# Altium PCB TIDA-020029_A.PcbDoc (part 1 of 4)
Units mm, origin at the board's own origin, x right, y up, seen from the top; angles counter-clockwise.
Board outline 267.5 x 53.5 mm, 2 copper layers (Top Layer, Bottom Layer), stack 1.575 mm thick; 255 components, 134 nets, 990 pads, 1977 vias.
Unrouted connection lines stored in the file: 9.
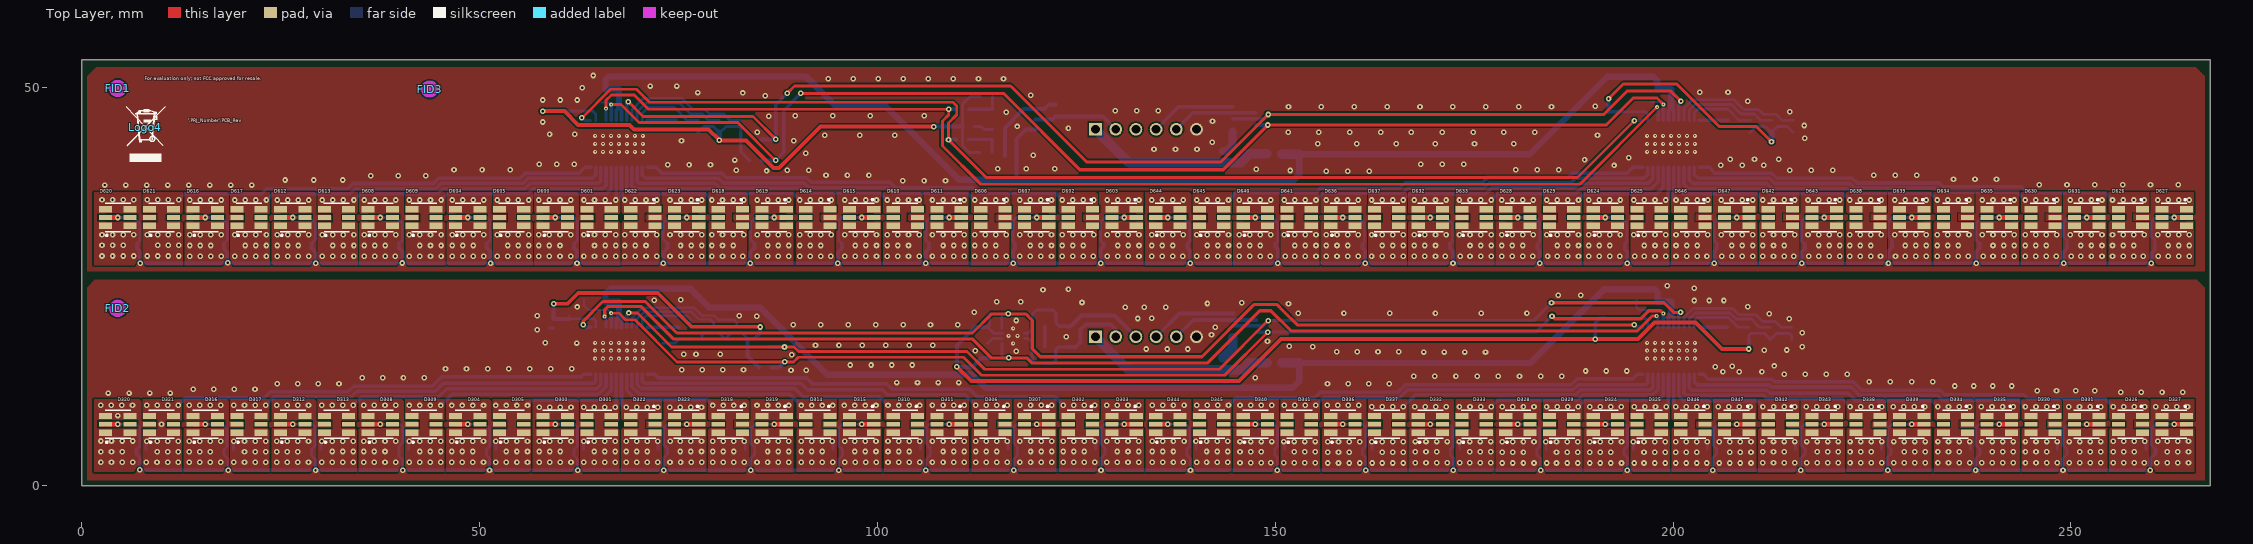
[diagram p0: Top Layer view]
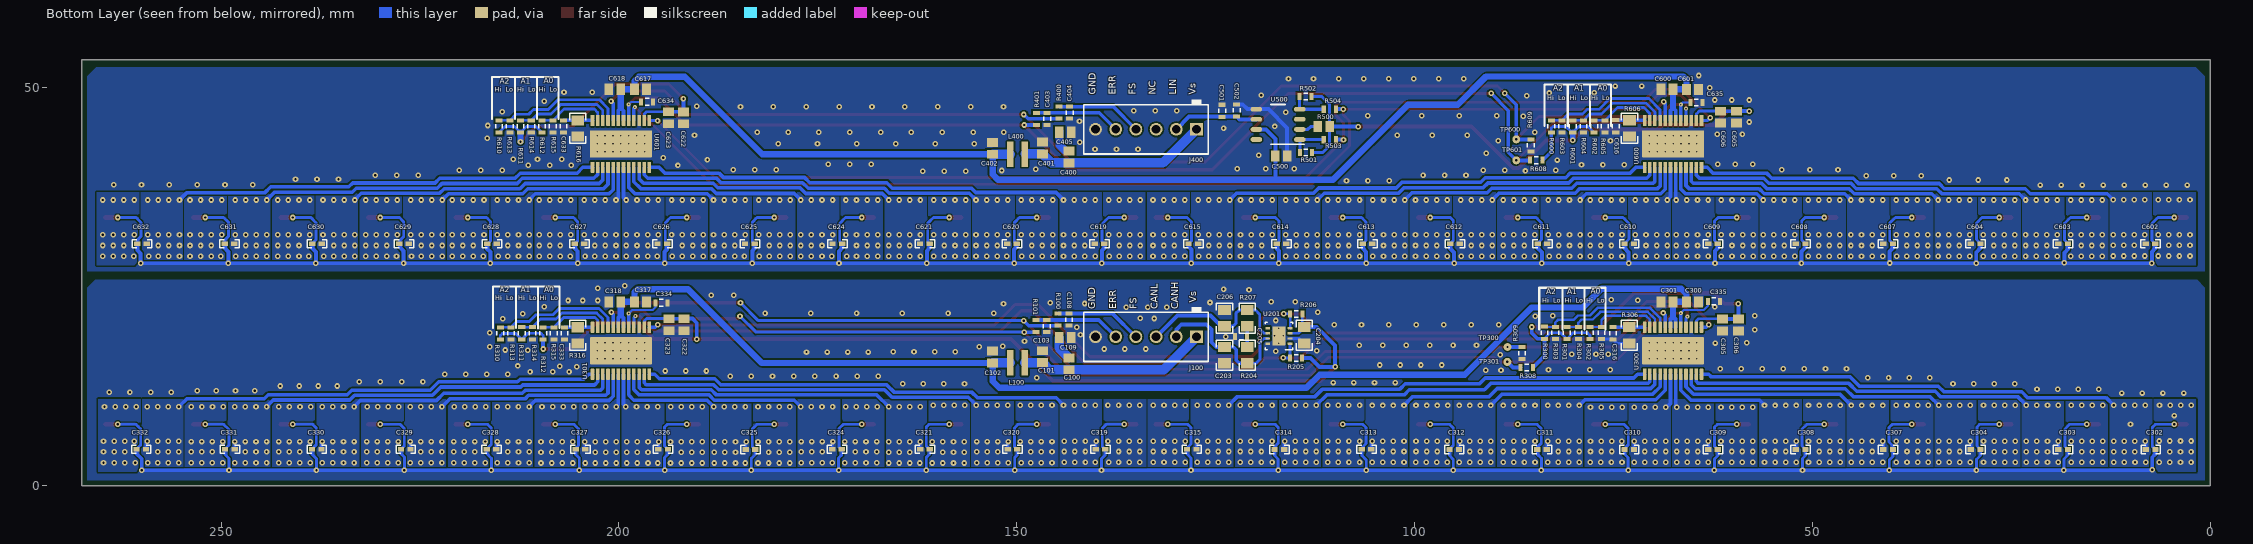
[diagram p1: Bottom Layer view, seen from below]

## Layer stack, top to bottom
Top Solder: solder mask 0.0102, Solder Resist, Dk 3.5
Top Layer: signal copper 0.0356
Dielectric1: core 1.5037, FR-4, Dk 4.8
Bottom Layer: signal copper 0.0356
Bottom Solder: solder mask 0.0102, Solder Resist, Dk 3.5

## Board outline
0,0 267.5,0 267.5,53.5 0,53.5

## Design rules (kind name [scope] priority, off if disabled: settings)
AcuteAngle [All] p1: minimum=4.50000000000000E+0001 checktracksonly=FALSE
AssemblyTestPointUsage [All] p1: valid=2
BoardOutlineClearance BoardOutlineClearance_MountingHoles [OnCopper and InComponentClass('Mounting Holes')] p1: gap=1 ignorepadtopadclearanceinfootprint=FALSE
BoardOutlineClearance BoardOutlineClearance_Poly [OnCopper and IsPoly] p2: gap=0.635 ignorepadtopadclearanceinfootprint=FALSE
BoardOutlineClearance [OnCopper and Not InComponentClass('Logo') and not InComponentClass('FiducialMark') and not InRegion(1000,500,4000,800) and not InPoly] p3: gap=1.5 ignorepadtopadclearanceinfootprint=FALSE
Clearance Clearance_Keepouts [((IsTrack Or IsArc) And Not InPoly) And IsFree and IsKeepOut vs ((IsTrack Or IsArc) And Not InPoly) And IsFree and IsKeepOut] p1: gap=0 ignorepadtopadclearanceinfootprint=FALSE
Clearance Clearance_Poly [InPolygon] p2: gap=0.2 ignorepadtopadclearanceinfootprint=TRUE
Clearance Clearance_FiducialMark [IsKeepOut and InComponentClass('FiducialMark') vs IsPad and InComponentClass('FiducialMark')] p3: gap=0 ignorepadtopadclearanceinfootprint=FALSE
Clearance [All] p4: gap=0.2 ignorepadtopadclearanceinfootprint=TRUE
ComponentClearance ComponentClearance_MountingHoles_FiducialMarks [InComponentClass('Mounting Holes') vs InComponentClass('FiducialMark')] p1: gap=1.27 collisioncheckmode=3 verticalgap=0.254 showdistances=FALSE
ComponentClearance ComponentClearance_Shunt [InComponentClass('Header') vs InComponentClass('Shunt')] p2: gap=0 collisioncheckmode=3 verticalgap=0 showdistances=FALSE
ComponentClearance ComponentClearance_Logo [InComponentClass('Logo')] p3: gap=1.27 collisioncheckmode=3 verticalgap=0.254 showdistances=FALSE
ComponentClearance ComponentClearance_ScrewToNut [(HasFootprint('NY PMS 440 0025 PH')) vs (HasFootprint('Keystone_1902C'))] p4: gap=0.127 collisioncheckmode=3 verticalgap=0.254 showdistances=FALSE
ComponentClearance ComponentClearance_MountingHoles [InComponentClass('Mounting Holes')] p5: gap=6.35 collisioncheckmode=3 verticalgap=2540 showdistances=FALSE
ComponentClearance ComponentClearance_SmallPassives [HasFootprint('0201*') or HasFootprint('0402*') or HasFootprint('0508') or HasFootprint('0603*') or HasFootprint('0612') or HasFootprint('0805*') or HasFootprint('0815*') or HasFootprint('0830*') or HasFootprint('1206*') or HasFootprint('1210*') or HasFootprint('1808*') or HasFootprint('1812*') or HasFootprint('1825*') or HasFootprint('2010*') or HasFootprint('2220*') or HasFootprint('2225*') or HasFootprint('2512*') or HasFootprint('2728*') or HasFootprint('3518*') vs HasFootprint('0201*') or HasFootprint('0402*') or HasFootprint('0508') or HasFootprint('0603*') or HasFootprint('0612') or HasFootprint('0805*') or HasFootprint('0815*') or HasFootprint('0830*') or HasFootprint('1206*') or HasFootprint('1210*') or HasFootprint('1808*') or HasFootprint('1812*') or HasFootprint('1825*') or HasFootprint('2010*') or HasFootprint('2220*') or HasFootprint('2225*') or HasFootprint('2512*') or HasFootprint('2728*') or HasFootprint('3518*')] p6: gap=0.38 collisioncheckmode=3 verticalgap=0.254 showdistances=FALSE
ComponentClearance ComponentClearance_THtoSMT [IsThruComponent vs IsSMTComponent] p7: gap=1.016 collisioncheckmode=3 verticalgap=0.762 showdistances=FALSE
ComponentClearance ComponentClearance_THtoTH [IsThruComponent vs IsThruComponent] p8: gap=0.762 collisioncheckmode=3 verticalgap=0.762 showdistances=FALSE
ComponentClearance [All] p9: gap=0.762 collisioncheckmode=3 verticalgap=0.254 showdistances=FALSE
DiffPairsRouting [All] p1: maxlimit=2.54 minlimit=0.254 mostfreqgap=0.254 toplayer_minwidth=0.381 toplayer_maxwidth=0.381 toplayer_prefwidth=0.381 bottomlayer_minwidth=0.381 bottomlayer_maxwidth=0.381 bottomlayer_prefwidth=0.381 maxuncoupledlength=25.4
FabricationTestPointUsage TestPointUsage [All] p1: valid=2 allowmultiple=FALSE
FabricationTestpoint Testpoint [All] p1: side=3 testpointundercomponent=TRUE minsize=1.016 maxsize=2.54 preferedsize=1.524 minholesize=0 maxholesize=1.016 preferedholesize=0.813 testpointgrid=0.025 allowsidetop=TRUE allowsidebottom=TRUE usegrid=TRUE gridtolerance=0
FanoutControl Fanout_LCC [IsLCC] p1: bgadir=Out bgaviamode=Centered fanoutstyle=Auto fanoutdirection=Alternating viagrid=0.025 // Fanout_LCC (Default Rule)
FanoutControl Fanout_BGA [IsBGA] p2: bgadir=Out bgaviamode=Centered fanoutstyle=Auto fanoutdirection=Alternating viagrid=0.025 // Fanout_BGA (Default Rule)
FanoutControl Fanout_Default [All] p4: bgadir=Out bgaviamode=Centered fanoutstyle=Auto fanoutdirection=Alternating viagrid=0.025 // Fanout_Default (Default Rule)
FanoutControl Fanout_Small [(CompPinCount < 5)] p5: bgadir=Out bgaviamode=Centered fanoutstyle=Auto fanoutdirection=OutThenIn viagrid=0.025 // Fanout_Small (Default Rule)
HoleSize [All] p1: absolutevalues=TRUE maxlimit=6.375 minlimit=0.2 maxpercent=80.000 minpercent=20.000
MinimumAnnularRing MinimumAnnularRing_ThermalPadVias [IsVia and InAnyComponent] p1: minimumring=0.15
MinimumAnnularRing [All] p2: minimumring=0.15
MinimumSolderMaskSliver MinimumSolderMaskSliver_Logo [InComponentClass('Logo') vs InComponentClass('Logo')] p1: minsoldermaskwidth=0.018
MinimumSolderMaskSliver [All] p2: minsoldermaskwidth=0.1
PlaneConnect [All] p1: planeconnectstyle=Direct reliefexpansion=0.254 reliefentries=4 reliefconductorwidth=0.254 reliefairgap=0.254
PolygonConnect [All] p1: connectstyle=Direct reliefconductorwidth=0.254 reliefentries=4 polygonreliefangle="90 Angle" airgapwidth=0.254
RoutingVias ThermalPadVias [IsVia and InAnyComponent] p1: holewidth=0.2 width=0.5 viastyle="Through Hole" minholewidth=0.2 minwidth=0.5 maxholewidth=0.33 maxwidth=0.6
RoutingVias [All] p2: holewidth=0.406 width=0.864 viastyle="Through Hole" minholewidth=0.2 minwidth=0.5 maxholewidth=1.016 maxwidth=1.651
SilkToBoardRegionClearance [Not ((IsComment or IsDesignator) And (Hide <> 'False')) and not InRegion(1000,500,4000,800)] p1:
SilkToSilkClearance SilkToSilkClearance_Pb-FreeLogo [(HasFootprint('Pb-Free_Overlay_Medium') OR HasFootprint('Pb-Free_Overlay_Small')) vs (HasFootprint('Pb-Free_Overlay_Medium') OR HasFootprint('Pb-Free_Overlay_Small'))] p1 off: silktosilkclearance=0
SilkToSilkClearance [All] p2 off: silktosilkclearance=0.1
SilkToSolderMaskClearance SilkToComponentPadClearance [(IsPad or IsFill or IsRegion) and InAnycomponent] p1 off: minsilkscreentomaskgap=0.127 clearancetoexposedcopper=TRUE
SilkToSolderMaskClearance "Silk to Solder Mask Opening" [All] p2 off: minsilkscreentomaskgap=0.1 clearancetoexposedcopper=FALSE
SolderMaskExpansion [All] p1: expansion=0.05
UnRoutedNet [All] p1: checkbadconnections=TRUE
Width [All] p1: maxlimit=2.54 minlimit=0.15 preferedwidth=0.35 checkconnectedcopper=TRUE
14 further rules are at their usual default settings.

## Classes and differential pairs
component class TIDA-020029_A_2: C400 C401 C402 C403 C404 C405 C500 C501 C502 C600 C601 C602 C603 C604 C605 C606 C607 C608 C609 C610 C611 C612 C613 C614 C615 C616 C617 C618 C619 C620 C621 C622 C623 C624 C625 C626 C627 C628 C629 C630 C631 C632 C633 C634 C635 D600 D601 D602 D603 D604 D605 D606 D607 D608 D609 D610 D611 D612 D613 D614 D615 D616 D617 D618 D619 D620 D621 D622 D623 D624 D625 D626 D627 D628 D629 D630 D631 D632 D633 D634 D635 D636 D637 D638 D639 D640 D641 D642 D643 D644 D645 D646 D647 J400 L400 R208 R400 R401 R500 R501 R502 R503 R504 R600 R601 R602 R603 R604 R605 R606 R608 R609 R610 R611 R612 R613 R614 R615 R616 TP600 TP601 U500 U600 U601
component class TIDA-020029_A_1: C100 C101 C102 C103 C108 C109 C203 C204 C205 C206 C300 C301 C302 C303 C304 C305 C306 C307 C308 C309 C310 C311 C312 C313 C314 C315 C316 C317 C318 C319 C320 C321 C322 C323 C324 C325 C326 C327 C328 C329 C330 C331 C332 C333 C334 C335 D300 D301 D302 D303 D304 D305 D306 D307 D308 D309 D310 D311 D312 D313 D314 D315 D316 D317 D318 D319 D320 D321 D322 D323 D324 D325 D326 D327 D328 D329 D330 D331 D332 D333 D334 D335 D336 D337 D338 D339 D340 D341 D342 D343 D344 D345 D346 D347 J100 L100 R100 R101 R204 R205 R206 R207 R300 R301 R302 R303 R304 R305 R306 R308 R309 R310 R311 R312 R313 R314 R315 R316 TP300 TP301 U201 U300 U301
component class TIDA-020029_A_3: FID1 FID2 FID3 Logo3 Logo4 ZZ1 ZZ2 ZZ3 ZZ4
component class FiducialMark: FID1 FID2 FID3
component class AssemblyNote: ZZ1 ZZ2 ZZ3 ZZ4

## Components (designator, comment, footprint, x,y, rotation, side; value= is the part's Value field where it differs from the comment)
C100 "CGA4J2X7R2A473K125AA" 0805L 143.408,15.298 r90 bottom value=0.047uF
C101 "CGA4J1X7R1V475K125AC" 0805L 146.761,16.213 r90 bottom value=4.7uF
C102 "CGA4J1X7R1V475K125AC" 0805L 153.035,16.162 r90 bottom value=4.7uF
C103 "CGA3E2X7R2A102K080AA" 0603S 146.228,20.048 r270 bottom value=1000pF
C108 "CGA3E2X7R2A102K080AA" 0603S 143.434,20.871 r270 bottom value=1000pF
C109 "CGA4J2X7R2A473K125AA" 0805L 143.891,18.6 r180 bottom value=0.047uF
C203 "CGA4J2X7R2A473K125AA" 0805_HV 123.876,16.391 r270 bottom value=0.047uF
C204 "C0805C104K5RACAUTO" 0805_HV 113.843,18.895 r270 bottom value=0.1uF
C205 "CGA3E2C0G1H103J080AA" 0603S 121.793,18.727 r0 bottom value=0.01uF
C206 "CGA4J2X7R2A473K125AA" 0805_HV 123.876,21.039 r90 bottom value=0.047uF
C300 "CGA4J1X7R1V475K125AC" 0805L 65.056,23.096 r180 bottom value=4.7uF
C301 "CGA4J2X8R1H104M125AA" 0805L 68.256,23.096 r0 bottom value=0.1uF
C302 "CGA2B2C0G1H102J050BA" 0402 7.459,4.535 r0 bottom value=1000pF
C303 "CGA2B2C0G1H102J050BA" 0402 18.459,4.535 r0 bottom value=1000pF
C304 "CGA2B2C0G1H102J050BA" 0402 29.459,4.535 r0 bottom value=1000pF
C305 "CGA4J1X7R1V475K125AC" 0805L 61.279,20.193 r270 bottom value=4.7uF
C306 "CGA4J2X8R1H104M125AA" 0805L 59.279,20.193 r270 bottom value=0.1uF
C307 "CGA2B2C0G1H102J050BA" 0402 40.459,4.535 r0 bottom value=1000pF
C308 "CGA2B2C0G1H102J050BA" 0402 51.459,4.535 r0 bottom value=1000pF
C309 "CGA2B2C0G1H102J050BA" 0402 62.459,4.535 r0 bottom value=1000pF
C310 "CGA2B2C0G1H102J050BA" 0402 73.004,4.535 r180 bottom value=1000pF
C311 "CGA2B2C0G1H102J050BA" 0402 83.972,4.535 r180 bottom value=1000pF
C312 "CGA2B2C0G1H102J050BA" 0402 95.004,4.535 r180 bottom value=1000pF
C313 "CGA2B2C0G1H102J050BA" 0402 106.02,4.561 r180 bottom value=1000pF
C314 "CGA2B2C0G1H102J050BA" 0402 116.992,4.535 r180 bottom value=1000pF
C315 "CGA2B2C0G1H102J050BA" 0402 128.004,4.561 r180 bottom value=1000pF
C316 "CGA3E2C0G1H103J080AA" 0603S 75.058,19.15 r90 bottom value=0.01uF
C317 "CGA4J1X7R1V475K125AC" 0805L 197.294,23.096 r180 bottom value=4.7uF
C318 "CGA4J2X8R1H104M125AA" 0805L 200.52,23.096 r0 bottom value=0.1uF
C319 "CGA2B2C0G1H102J050BA" 0402 139.471,4.561 r0 bottom value=1000pF
C320 "CGA2B2C0G1H102J050BA" 0402 150.546,4.569 r0 bottom value=1000pF
C321 "CGA2B2C0G1H102J050BA" 0402 161.544,4.561 r0 bottom value=1000pF
C322 "CGA4J1X7R1V475K125AC" 0805L 191.828,20.218 r270 bottom value=4.7uF
C323 "CGA4J2X8R1H104M125AA" 0805L 193.73,20.218 r270 bottom value=0.1uF
C324 "CGA2B2C0G1H102J050BA" 0402 172.593,4.561 r0 bottom value=1000pF
C325 "CGA2B2C0G1H102J050BA" 0402 183.459,4.535 r0 bottom value=1000pF
C326 "CGA2B2C0G1H102J050BA" 0402 194.439,4.561 r0 bottom value=1000pF
C327 "CGA2B2C0G1H102J050BA" 0402 204.85,4.561 r180 bottom value=1000pF
C328 "CGA2B2C0G1H102J050BA" 0402 216.006,4.561 r180 bottom value=1000pF
C329 "CGA2B2C0G1H102J050BA" 0402 226.804,4.561 r180 bottom value=1000pF
C330 "CGA2B2C0G1H102J050BA" 0402 237.988,4.561 r180 bottom value=1000pF
C331 "CGA2B2C0G1H102J050BA" 0402 248.912,4.561 r180 bottom value=1000pF
C332 "CGA2B2C0G1H102J050BA" 0402 260.045,4.561 r180 bottom value=1000pF
C333 "CGA3E2C0G1H103J080AA" 0603S 206.836,19.134 r90 bottom value=0.01uF
C334 "CGA3E2X7R2A102K080AA" 0603S 194.669,22.966 r180 bottom value=1000pF
C335 "CGA3E2X7R2A102K080AA" 0603S 62.359,23.165 r180 bottom value=1000pF
C400 "CGA4J2X7R2A473K125AA" 0805L 143.408,41.308 r90 bottom value=0.047uF
C401 "CGA4J1X7R1V475K125AC" 0805L 146.761,42.435 r90 bottom value=4.7uF
C402 "CGA4J1X7R1V475K125AC" 0805L 153.035,42.385 r90 bottom value=4.7uF
C403 "CGA3E2X7R2A102K080AA" 0603S 146.177,46.09 r270 bottom value=1000pF
C404 "CGA3E2X7R2A102K080AA" 0603S 143.341,46.877 r270 bottom value=1000pF
C405 "CGA4J2X7R2A473K125AA" 0805L 143.891,44.413 r180 bottom value=0.047uF
C500 "CGA4J2X8R1H104M125AA" 0805L 116.75,41.448 r180 bottom value=0.1uF
C501 "CGA3E2NP01H101J080AA" 0603S 124.181,47.106 r90 bottom value=100pF
C502 "CGA3E2NP01H101J080AA" 0603S 122.352,47.157 r90 bottom value=100pF
C600 "CGA4J1X7R1V475K125AC" 0805L 68.256,49.824 r0 bottom value=4.7uF
C601 "CGA4J2X8R1H104M125AA" 0805L 65.056,49.798 r180 bottom value=0.1uF
C602 "CGA2B2C0G1H102J050BA" 0402 7.5,30.4 r0 bottom value=1000pF
C603 "CGA2B2C0G1H102J050BA" 0402 18.459,30.4 r0 bottom value=1000pF
C604 "CGA2B2C0G1H102J050BA" 0402 29.459,30.4 r0 bottom value=1000pF
C605 "CGA4J1X7R1V475K125AC" 0805L 59.546,46.311 r270 bottom value=4.7uF
C606 "CGA4J2X8R1H104M125AA" 0805L 61.546,46.311 r270 bottom value=0.1uF
C607 "CGA2B2C0G1H102J050BA" 0402 40.459,30.4 r0 bottom value=1000pF
C608 "CGA2B2C0G1H102J050BA" 0402 51.459,30.4 r0 bottom value=1000pF
C609 "CGA2B2C0G1H102J050BA" 0402 62.459,30.4 r0 bottom value=1000pF
C610 "CGA2B2C0G1H102J050BA" 0402 73.004,30.4 r180 bottom value=1000pF
C611 "CGA2B2C0G1H102J050BA" 0402 83.9,30.4 r180 bottom value=1000pF
C612 "CGA2B2C0G1H102J050BA" 0402 94.919,30.4 r180 bottom value=1000pF
C613 "CGA2B2C0G1H102J050BA" 0402 105.9,30.4 r180 bottom value=1000pF
C614 "CGA2B2C0G1H102J050BA" 0402 116.7,30.4 r180 bottom value=1000pF
C615 "CGA2B2C0G1H102J050BA" 0402 127.8,30.4 r180 bottom value=1000pF
C616 "CGA3E2C0G1H103J080AA" 0603S 74.701,45.166 r90 bottom value=0.01uF
C617 "CGA4J1X7R1V475K125AC" 0805L 197.294,49.824 r180 bottom value=4.7uF
C618 "CGA4J2X8R1H104M125AA" 0805L 200.52,49.824 r0 bottom value=0.1uF
C619 "CGA2B2C0G1H102J050BA" 0402 139.579,30.4 r0 bottom value=1000pF
C620 "CGA2B2C0G1H102J050BA" 0402 150.613,30.4 r0 bottom value=1000pF
C621 "CGA2B2C0G1H102J050BA" 0402 161.55,30.4 r0 bottom value=1000pF
C622 "CGA4J1X7R1V475K125AC" 0805L 191.893,46.217 r270 bottom value=4.7uF
C623 "CGA4J2X8R1H104M125AA" 0805L 193.777,46.235 r270 bottom value=0.1uF
C624 "CGA2B2C0G1H102J050BA" 0402 172.55,30.4 r0 bottom value=1000pF
C625 "CGA2B2C0G1H102J050BA" 0402 183.55,30.4 r0 bottom value=1000pF
C626 "CGA2B2C0G1H102J050BA" 0402 194.55,30.4 r0 bottom value=1000pF
C627 "CGA2B2C0G1H102J050BA" 0402 204.95,30.4 r180 bottom value=1000pF
C628 "CGA2B2C0G1H102J050BA" 0402 215.95,30.4 r180 bottom value=1000pF
C629 "CGA2B2C0G1H102J050BA" 0402 227,30.4 r180 bottom value=1000pF
C630 "CGA2B2C0G1H102J050BA" 0402 237.95,30.4 r180 bottom value=1000pF
C631 "CGA2B2C0G1H102J050BA" 0402 248.95,30.4 r180 bottom value=1000pF
C632 "CGA2B2C0G1H102J050BA" 0402 259.95,30.4 r180 bottom value=1000pF
C633 "CGA3E2C0G1H103J080AA" 0603S 206.963,45.15 r90 bottom value=0.01uF
C634 "CGA3E2X7R2A102K080AA" 0603S 196.468,48.241 r180 bottom value=1000pF
C635 "CGA3E2X7R2A102K080AA" 0603S 64.556,48.165 r180 bottom value=1000pF
D300 "LR G6SP-CBEA-1-1-Z" LED_LR_G6SP 59.5,7.7 r90 top value=Red
D301 "LR G6SP-CBEA-1-1-Z" LED_LR_G6SP 65,7.7 r90 top value=Red
D302 "LR G6SP-CBEA-1-1-Z" LED_LR_G6SP 125.5,7.7 r270 top value=Red
D303 "LR G6SP-CBEA-1-1-Z" LED_LR_G6SP 131,7.7 r270 top value=Red
D304 "LR G6SP-CBEA-1-1-Z" LED_LR_G6SP 48.5,7.7 r90 top value=Red
D305 "LR G6SP-CBEA-1-1-Z" LED_LR_G6SP 54,7.7 r90 top value=Red
D306 "LR G6SP-CBEA-1-1-Z" LED_LR_G6SP 114.5,7.7 r270 top value=Red
D307 "LR G6SP-CBEA-1-1-Z" LED_LR_G6SP 120,7.7 r270 top value=Red
D308 "LR G6SP-CBEA-1-1-Z" LED_LR_G6SP 37.5,7.7 r90 top value=Red
D309 "LR G6SP-CBEA-1-1-Z" LED_LR_G6SP 43,7.7 r90 top value=Red
D310 "LR G6SP-CBEA-1-1-Z" LED_LR_G6SP 103.5,7.7 r270 top value=Red
D311 "LR G6SP-CBEA-1-1-Z" LED_LR_G6SP 109,7.7 r270 top value=Red
D312 "LR G6SP-CBEA-1-1-Z" LED_LR_G6SP 26.5,7.7 r90 top value=Red
D313 "LR G6SP-CBEA-1-1-Z" LED_LR_G6SP 32,7.7 r90 top value=Red
D314 "LR G6SP-CBEA-1-1-Z" LED_LR_G6SP 92.5,7.7 r270 top value=Red
D315 "LR G6SP-CBEA-1-1-Z" LED_LR_G6SP 98,7.7 r270 top value=Red
D316 "LR G6SP-CBEA-1-1-Z" LED_LR_G6SP 15.5,7.7 r90 top value=Red
D317 "LR G6SP-CBEA-1-1-Z" LED_LR_G6SP 21,7.7 r90 top value=Red
D318 "LR G6SP-CBEA-1-1-Z" LED_LR_G6SP 81.5,7.7 r270 top value=Red
D319 "LR G6SP-CBEA-1-1-Z" LED_LR_G6SP 87,7.7 r270 top value=Red
D320 "LR G6SP-CBEA-1-1-Z" LED_LR_G6SP 4.5,7.7 r90 top value=Red
D321 "LR G6SP-CBEA-1-1-Z" LED_LR_G6SP 10,7.7 r90 top value=Red
D322 "LR G6SP-CBEA-1-1-Z" LED_LR_G6SP 70.5,7.7 r270 top value=Red
D323 "LR G6SP-CBEA-1-1-Z" LED_LR_G6SP 76,7.7 r270 top value=Red
D324 "LR G6SP-CBEA-1-1-Z" LED_LR_G6SP 191.5,7.7 r90 top value=Red
D325 "LR G6SP-CBEA-1-1-Z" LED_LR_G6SP 197,7.7 r90 top value=Red
D326 "LR G6SP-CBEA-1-1-Z" LED_LR_G6SP 257.5,7.7 r270 top value=Red
D327 "LR G6SP-CBEA-1-1-Z" LED_LR_G6SP 263,7.7 r270 top value=Red
D328 "LR G6SP-CBEA-1-1-Z" LED_LR_G6SP 180.5,7.7 r90 top value=Red
D329 "LR G6SP-CBEA-1-1-Z" LED_LR_G6SP 186,7.7 r90 top value=Red
D330 "LR G6SP-CBEA-1-1-Z" LED_LR_G6SP 246.5,7.7 r270 top value=Red
D331 "LR G6SP-CBEA-1-1-Z" LED_LR_G6SP 252,7.7 r270 top value=Red
D332 "LR G6SP-CBEA-1-1-Z" LED_LR_G6SP 169.5,7.7 r90 top value=Red
D333 "LR G6SP-CBEA-1-1-Z" LED_LR_G6SP 175,7.7 r90 top value=Red
D334 "LR G6SP-CBEA-1-1-Z" LED_LR_G6SP 235.5,7.7 r270 top value=Red
D335 "LR G6SP-CBEA-1-1-Z" LED_LR_G6SP 241,7.7 r270 top value=Red
D336 "LR G6SP-CBEA-1-1-Z" LED_LR_G6SP 158.5,7.7 r90 top value=Red
D337 "LR G6SP-CBEA-1-1-Z" LED_LR_G6SP 164,7.7 r90 top value=Red
D338 "LR G6SP-CBEA-1-1-Z" LED_LR_G6SP 224.5,7.7 r270 top value=Red
D339 "LR G6SP-CBEA-1-1-Z" LED_LR_G6SP 230,7.7 r270 top value=Red
D340 "LR G6SP-CBEA-1-1-Z" LED_LR_G6SP 147.5,7.7 r90 top value=Red
D341 "LR G6SP-CBEA-1-1-Z" LED_LR_G6SP 153,7.7 r90 top value=Red
D342 "LR G6SP-CBEA-1-1-Z" LED_LR_G6SP 213.5,7.7 r270 top value=Red
D343 "LR G6SP-CBEA-1-1-Z" LED_LR_G6SP 219,7.7 r270 top value=Red
D344 "LR G6SP-CBEA-1-1-Z" LED_LR_G6SP 136.5,7.7 r90 top value=Red
D345 "LR G6SP-CBEA-1-1-Z" LED_LR_G6SP 142,7.7 r90 top value=Red
D346 "LR G6SP-CBEA-1-1-Z" LED_LR_G6SP 202.5,7.7 r270 top value=Red
D347 "LR G6SP-CBEA-1-1-Z" LED_LR_G6SP 208,7.7 r270 top value=Red
D600 "LR G6SP-CBEA-1-1-Z" LED_LR_G6SP 59.5,33.7 r90 top value=Red
D601 "LR G6SP-CBEA-1-1-Z" LED_LR_G6SP 65,33.7 r90 top value=Red
D602 "LR G6SP-CBEA-1-1-Z" LED_LR_G6SP 125.5,33.7 r270 top value=Red
D603 "LR G6SP-CBEA-1-1-Z" LED_LR_G6SP 131,33.7 r270 top value=Red
D604 "LR G6SP-CBEA-1-1-Z" LED_LR_G6SP 48.5,33.7 r90 top value=Red
D605 "LR G6SP-CBEA-1-1-Z" LED_LR_G6SP 54,33.7 r90 top value=Red
D606 "LR G6SP-CBEA-1-1-Z" LED_LR_G6SP 114.5,33.7 r270 top value=Red
D607 "LR G6SP-CBEA-1-1-Z" LED_LR_G6SP 120,33.7 r270 top value=Red
D608 "LR G6SP-CBEA-1-1-Z" LED_LR_G6SP 37.5,33.7 r90 top value=Red
D609 "LR G6SP-CBEA-1-1-Z" LED_LR_G6SP 43,33.7 r90 top value=Red
D610 "LR G6SP-CBEA-1-1-Z" LED_LR_G6SP 103.5,33.7 r270 top value=Red
D611 "LR G6SP-CBEA-1-1-Z" LED_LR_G6SP 109,33.7 r270 top value=Red
D612 "LR G6SP-CBEA-1-1-Z" LED_LR_G6SP 26.5,33.7 r90 top value=Red
D613 "LR G6SP-CBEA-1-1-Z" LED_LR_G6SP 32,33.7 r90 top value=Red
D614 "LR G6SP-CBEA-1-1-Z" LED_LR_G6SP 92.5,33.7 r270 top value=Red
D615 "LR G6SP-CBEA-1-1-Z" LED_LR_G6SP 98,33.7 r270 top value=Red
D616 "LR G6SP-CBEA-1-1-Z" LED_LR_G6SP 15.5,33.7 r90 top value=Red
D617 "LR G6SP-CBEA-1-1-Z" LED_LR_G6SP 21,33.7 r90 top value=Red
D618 "LR G6SP-CBEA-1-1-Z" LED_LR_G6SP 81.5,33.7 r270 top value=Red
D619 "LR G6SP-CBEA-1-1-Z" LED_LR_G6SP 87,33.7 r270 top value=Red
D620 "LR G6SP-CBEA-1-1-Z" LED_LR_G6SP 4.5,33.7 r90 top value=Red
D621 "LR G6SP-CBEA-1-1-Z" LED_LR_G6SP 10,33.7 r90 top value=Red
D622 "LR G6SP-CBEA-1-1-Z" LED_LR_G6SP 70.5,33.7 r270 top value=Red
D623 "LR G6SP-CBEA-1-1-Z" LED_LR_G6SP 76,33.7 r270 top value=Red
D624 "LR G6SP-CBEA-1-1-Z" LED_LR_G6SP 191.5,33.7 r90 top value=Red
D625 "LR G6SP-CBEA-1-1-Z" LED_LR_G6SP 197,33.7 r90 top value=Red
D626 "LR G6SP-CBEA-1-1-Z" LED_LR_G6SP 257.5,33.7 r270 top value=Red
D627 "LR G6SP-CBEA-1-1-Z" LED_LR_G6SP 263,33.7 r270 top value=Red
D628 "LR G6SP-CBEA-1-1-Z" LED_LR_G6SP 180.5,33.7 r90 top value=Red
D629 "LR G6SP-CBEA-1-1-Z" LED_LR_G6SP 186,33.7 r90 top value=Red
D630 "LR G6SP-CBEA-1-1-Z" LED_LR_G6SP 246.5,33.7 r270 top value=Red
D631 "LR G6SP-CBEA-1-1-Z" LED_LR_G6SP 252,33.7 r270 top value=Red
D632 "LR G6SP-CBEA-1-1-Z" LED_LR_G6SP 169.5,33.7 r90 top value=Red
D633 "LR G6SP-CBEA-1-1-Z" LED_LR_G6SP 175,33.7 r90 top value=Red
D634 "LR G6SP-CBEA-1-1-Z" LED_LR_G6SP 235.5,33.7 r270 top value=Red
D635 "LR G6SP-CBEA-1-1-Z" LED_LR_G6SP 241,33.7 r270 top value=Red
D636 "LR G6SP-CBEA-1-1-Z" LED_LR_G6SP 158.5,33.7 r90 top value=Red
D637 "LR G6SP-CBEA-1-1-Z" LED_LR_G6SP 164,33.7 r90 top value=Red
D638 "LR G6SP-CBEA-1-1-Z" LED_LR_G6SP 224.5,33.7 r270 top value=Red
D639 "LR G6SP-CBEA-1-1-Z" LED_LR_G6SP 230,33.7 r270 top value=Red
D640 "LR G6SP-CBEA-1-1-Z" LED_LR_G6SP 147.5,33.7 r90 top value=Red
D641 "LR G6SP-CBEA-1-1-Z" LED_LR_G6SP 153,33.7 r90 top value=Red
D642 "LR G6SP-CBEA-1-1-Z" LED_LR_G6SP 213.5,33.7 r270 top value=Red
D643 "LR G6SP-CBEA-1-1-Z" LED_LR_G6SP 219,33.7 r270 top value=Red
D644 "LR G6SP-CBEA-1-1-Z" LED_LR_G6SP 136.5,33.7 r90 top value=Red
D645 "LR G6SP-CBEA-1-1-Z" LED_LR_G6SP 142,33.7 r90 top value=Red
D646 "LR G6SP-CBEA-1-1-Z" LED_LR_G6SP 202.5,33.7 r270 top value=Red
D647 "LR G6SP-CBEA-1-1-Z" LED_LR_G6SP 208,33.7 r270 top value=Red
FID1 "Fiducial" Fiducial10-20 4.496,49.918 r0 top
FID2 "Fiducial" Fiducial10-20 4.496,22.276 r0 top
FID3 "Fiducial" Fiducial10-20 43.713,49.841 r0 top
J100 "1725698" Phoenix_1725698 133.75,18.7 r0 bottom
J400 "1725698" Phoenix_1725698 133.75,44.782 r0 bottom
L100 "XEL3530-122MEC" FP-XEL3530-122MEC_SMT_IND_3MM2_3MM5-MFG 149.9,15.425 r0 bottom
L400 "XEL3530-122MEC" FP-XEL3530-122MEC_SMT_IND_3MM2_3MM5-MFG 149.9,41.635 r0 bottom
Logo3 "FCC disclaimer" FCC_disclaimer 65.938,83.007 r0 top
Logo4 "WEEE logo" WEEE_Minimum 7.976,45.06 r0 top
R100 "RCS06030000Z0EA" 0603S 144.805,20.871 r270 bottom value=0
R101 "RCS06030000Z0EA" 0603S 147.588,20.048 r270 bottom value=0
R204 "CRCW080560R4FKEA" 0805_HV 121.031,16.391 r270 bottom value=60.4
R205 "RMCF0603FT10K0" 0603S 114.884,16.048 r180 bottom value=10.0k
R206 "RMCF0603FT10K0" 0603S 114.859,21.572 r180 bottom value=10.0k
R207 "CRCW080560R4FKEA" 0805_HV 121.031,21.039 r270 bottom value=60.4
R300 "RMCF0603FT10K0" 0603S 83.648,19.21 r270 bottom value=10.0k
R301 "RMCF0603FT10K0" 0603S 80.85,19.2 r270 bottom value=10.0k
R302 "RMCF0603FT10K0" 0603S 77.95,19.2 r270 bottom value=10.0k
R303 "RMCF0603FT10K0" 0603S 82.3,19.2 r90 bottom value=10.0k
R304 "RMCF0603FT10K0" 0603S 79.4,19.2 r90 bottom value=10.0k
R305 "RMCF0603FT10K0" 0603S 76.5,19.2 r90 bottom value=10.0k
R306 "ERJ-6ENF1242V" 0805_HV 73,18.9 r90 bottom value=12.4k
R308 "RMCF0603FT10K0" 0603S 85.894,14.842 r180 bottom value=10.0k
R309 "RMCF0603FT10K0" 0603S 86.479,16.659 r90 bottom value=10.0k
R310 "RMCF0603FT10K0" 0603S 214.913,19.134 r270 bottom value=10.0k
R311 "RMCF0603FT10K0" 0603S 212.221,19.144 r270 bottom value=10.0k
R312 "RMCF0603FT10K0" 0603S 209.529,19.134 r270 bottom value=10.0k
R313 "RMCF0603FT10K0" 0603S 213.567,19.134 r90 bottom value=10.0k
R314 "RMCF0603FT10K0" 0603S 210.875,19.144 r90 bottom value=10.0k
R315 "RMCF0603FT10K0" 0603S 208.185,19.135 r90 bottom value=10.0k
R316 "ERJ-6ENF1242V" 0805_HV 205.185,18.88 r90 bottom value=12.4k
R400 "RCS06030000Z0EA" 0603S 144.678,46.877 r270 bottom value=0
R401 "RCS06030000Z0EA" 0603S 147.523,46.09 r270 bottom value=0
R500 "ERJ-P06F4701V" 0805L 111.404,45.125 r0 bottom value=4.70k
R501 "RMCF0603FT10K0" 0603S 113.64,41.873 r180 bottom value=10.0k
R502 "RMCF0603FT10K0" 0603S 113.69,48.909 r180 bottom value=10.0k
R503 "CRCW060322R0JNEA" 0603S 110.646,43.474 r0 bottom value=22
R504 "CRCW060322R0JNEA" 0603S 110.646,47.309 r0 bottom value=22
R600 "RMCF0603FT10K0" 0603S 82.804,45.15 r270 bottom value=10.0k
R601 "RMCF0603FT10K0" 0603S 80.112,45.15 r270 bottom value=10.0k
R602 "RMCF0603FT10K0" 0603S 77.419,45.15 r270 bottom value=10.0k
R603 "RMCF0603FT10K0" 0603S 81.458,45.15 r90 bottom value=10.0k
R604 "RMCF0603FT10K0" 0603S 78.765,45.15 r90 bottom value=10.0k
R605 "RMCF0603FT10K0" 0603S 76.073,45.15 r90 bottom value=10.0k
R606 "ERJ-6ENF1242V" 0805_HV 72.974,44.906 r90 bottom value=12.4k
R608 "RMCF0603FT10K0" 0603S 84.693,40.901 r180 bottom value=10.0k
R609 "RMCF0603FT10K0" 0603S 85.379,42.755 r90 bottom value=10.0k
R610 "RMCF0603FT10K0" 0603S 215.066,45.15 r270 bottom value=10.0k
R611 "RMCF0603FT10K0" 0603S 212.373,45.15 r270 bottom value=10.0k
R612 "RMCF0603FT10K0" 0603S 209.681,45.15 r270 bottom value=10.0k
R613 "RMCF0603FT10K0" 0603S 213.72,45.15 r90 bottom value=10.0k
R614 "RMCF0603FT10K0" 0603S 211.027,45.15 r90 bottom value=10.0k
R615 "RMCF0603FT10K0" 0603S 208.309,45.15 r90 bottom value=10.0k
R616 "ERJ-6ENF1242V" 0805_HV 205.185,44.896 r90 bottom value=12.4k
TP300 "TP_SM_1MM" TP_SM_1MM 88.309,17.421 r270 bottom
TP301 "TP_SM_1MM" TP_SM_1MM 88.332,15.542 r270 bottom
TP600 "TP_SM_1MM" TP_SM_1MM 87.208,43.517 r270 bottom
TP601 "TP_SM_1MM" TP_SM_1MM 87.208,40.875 r270 bottom
U201 "TCAN1044DRBTQ1" DRB0008F 117.043,18.819 r0 bottom
U300 "TPS929120QPWPRQ1" PWP0024P_N 67.5,16.95 r270 bottom
U301 "TPS929120QPWPRQ1" PWP0024P_N 199.75,16.95 r270 bottom
U500 "TLIN1029DRQ1" D0008A_N 117.145,45.404 r0 bottom
U600 "TPS929120QPWPRQ1" PWP0024P_N 67.5,42.95 r270 bottom
U601 "TPS929120QPWPRQ1" PWP0024P_N 199.75,42.95 r270 bottom
ZZ1 "This Assembly Note is for PCB labels only" AssemblyNoteLabel 4.699,100.025 r0 top
ZZ2 "These assemblies are ESD sensitive, ESD precautions shall be observed." AssemblyNote 4.699,97.259 r0 top
ZZ3 "These assemblies must be clean and free from flux and all contaminants. Use of no clean flux is not acceptable." AssemblyNote 4.699,95.01 r0 top
ZZ4 "These assemblies must comply with workmanship standards IPC-A-610 Class 2, unless otherwise specified." AssemblyNote 4.699,92.761 r0 top

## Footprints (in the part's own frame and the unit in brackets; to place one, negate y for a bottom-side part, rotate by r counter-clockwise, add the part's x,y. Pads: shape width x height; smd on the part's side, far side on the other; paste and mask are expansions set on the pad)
0402 [mm] "0402 from SM-752 data"
  rect 0.8x0.6 smd: 1(-0.6,0) 2(0.6,0)
  silkscreen extent -1.22,-0.52 1.22,0.52, body extent -0.55,-0.3 0.55,0.3, height 0.6
0603S [mil]
  rect 20x35 smd: 1(-30,0) 2(30,0)
  silkscreen extent -10,-17 10,17, body extent -34,-19 34,19, height 39
0805_HV [mil] "0805 with 30mil clearance between pads"
  rect 50x63 smd: 1(-40,0) 2(40,0)
  silkscreen extent -74,-40 74,40, body extent -43,-29 43,29, height 57
0805L [mm] "0805 from SM-752 data"
  rect 1.1x1.4 smd: 1(-0.75,0) 2(0.75,0)
  body extent -1.1,-0.72 1.1,0.72, height 1.45
AssemblyNote [mm] "Assembly Note"
AssemblyNoteLabel [mm] "Assembly Note for PCB Labels"
D0008A_N [mm] "SOIC, 8-Leads, Body 4.9x3.9mm, Pitch 1.27mm, IPC Medium Density"
  oval 1.45x0.6 smd: 1(-2.725,1.905) 2(-2.725,0.635) 3(-2.725,-0.635) 4(-2.725,-1.905) 5(2.725,-1.905) 6(2.725,-0.635) 7(2.725,0.635) 8(2.725,1.905)
  silkscreen extent -3.3,-2.5 0.9,2.5, body extent -3,-2.45 3,2.45, height 1.63
DRB0008F [mm] "SON, 8-Leads, Body 3x3mm, Pitch 0.65mm, Thermal Pad 2.4x1.6mm, TI Recommended"
  rrect33% 0.6x0.3 smd: 1(-1.4,0.975) 2(-1.4,0.325) 3(-1.4,-0.325) 4(-1.4,-0.975) 5(1.4,-0.975) 6(1.4,-0.325) 7(1.4,0.325) 8(1.4,0.975)
  rrect9% 1.47x1.07 on Bottom Paste: 9(0,-0.635) 9(0,0.635)
  rrect6% 1.6x2.4 smd paste-1.2: 9(0,0)
  silkscreen extent -1.73,-1.73 1.73,1.73, body extent -1.5,-1.5 1.5,1.5, height 0.77
FCC_disclaimer [mm]
Fiducial10-20 [mm]
  round 1 smd mask+0.5: 1(0,0)
  Top Layer keep-out circle w1.178: c0,0 r0.5
FP-XEL3530-122MEC_SMT_IND_3MM2_3MM5-MFG [mm]
  rrect12% 0.81x3.2 smd paste+0 mask+0: 1(-0.9,0) 2(0.9,0)
  body extent -1.6,-1.75 1.6,1.75, height 3
LED_LR_G6SP [mm] "OSRAM"
  rect 0.8x1.65 smd: 1(-1.05,1.525) 3(1.05,1.525) 4(1.05,-1.525) 6(-1.05,-1.525)
  rect 0.6x1.65 smd: 2(0,1.525) 5(0,-1.525)
  silkscreen extent -2.35,-1.63 1.78,1.6, body extent -1.75,-1.6 1.75,1.6, height 2.12
Phoenix_1725698 [mm] "Terminal Block, 6x1, 2.54mm, TH"
  rect 1.6x1.6 hole 1.1: 1(-6.35,0)
  round 1.6 hole 1.1: 2(-3.81,0) 3(-1.27,0) 4(1.27,0) 5(3.81,0) 6(6.35,0)
  silkscreen extent -7.85,-3.75 7.85,3.1, body extent -7.85,-3.1 7.85,3.1, height 8.51
PWP0024P_N [mm] "HTTSOP-24"
  rrect22% 1.4x0.45 smd: 1(-2.95,3.575) 2(-2.95,2.925) 3(-2.95,2.275) 4(-2.95,1.625) 5(-2.95,0.975) 6(-2.95,0.325) 7(-2.95,-0.325) 8(-2.95,-0.975) 9(-2.95,-1.625) 10(-2.95,-2.275) 11(-2.95,-2.925) 12(-2.95,-3.575) 13(2.95,-3.575) 14(2.95,-2.925) 15(2.95,-2.275) 16(2.95,-1.625) 17(2.95,-0.975) 18(2.95,-0.325) 19(2.95,0.325) 20(2.95,0.975) 21(2.95,1.625) 22(2.95,2.275) 23(2.95,2.925) 24(2.95,3.575)
  rrect6% 3.4x7.8 smd paste-2 mask-2: 25(0,0)
  body extent -3.21,-3.9 3.21,3.9, height 1.2
TP_SM_1MM [mm] "1mm Test Point, SMT"
  round 1 smd paste-0.5: 1(0,0)
WEEE_Minimum [mm] "WEEElie bin"
  silkscreen extent -2.42,-4.38 2.52,2.65

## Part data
C100 C109 C203 C206 C400 C405: library part CMP-0007970-1, "CAP, CERM, 0.047 uF, 100 V, +/- 10%, X7R, AEC-Q200 Grade 1, 0805", Cap_Case=0805, Manufacturer=TDK, Supplier Part Number 1=445-5825-1-ND, TempCo=X7R, Tolerance_%=10%, Value1="0.049089 ohm", Value2=100V, ValueDisplayed=0.047uF
C101 C102 C300 C305 C317 C322 C401 C402 C600 C605 C617 C622: library part CMP-0007964-1, "CAP, CERM, 4.7 uF, 35 V, +/- 10%, X7R, AEC-Q200 Grade 1, 0805", Cap_Case=0805, Manufacturer=TDK, Supplier Part Number 1=810-CGA4J1X7R1V475K125AC, TempCo=X7R, Tolerance_%=10%, Value1="0.002346 ohm", Value2=35V, ValueDisplayed=4.7uF
C103 C108 C334 C335 C403 C404 C634 C635: library part CMP-0007081-1, "CAP, CERM, 1000 pF, 100 V, +/- 10%, X7R, AEC-Q200 Grade 1, 0603", Cap_Case=0603, Manufacturer=TDK, Supplier Part Number 1=445-5806-1-ND, TempCo=X7R, Tolerance_%=10%, Value1="1.97137 ohm", Value2=100V, ValueDisplayed=1000pF
C204: library part CMP-0007725-1, "CAP, CERM, 0.1 uF, 50 V, +/- 10%, X7R, AEC-Q200 Grade 0, 0805", Cap_Case=0805, Manufacturer=Kemet, Supplier Part Number 1=399-6928-1-ND, TempCo=X7R, Tolerance_%=10%, Value1=Unknown, Value2=50V, ValueDisplayed=0.1uF
C205 C316 C333 C616 C633: library part CMP-0007070-1, "CAP, CERM, 0.01 uF, 50 V, +/- 5%, C0G/NP0, AEC-Q200 Grade 1, 0603", Cap_Case=0603, Manufacturer=TDK, Supplier Part Number 1=445-6916-1-ND, TempCo=C0G/NP0, Tolerance_%=5%, Value1=Unknown, Value2=50V, ValueDisplayed=0.01uF
C301 C306 C318 C323 C500 C601 C606 C618 C623: library part CMP-0007971-1, "CAP, CERM, 0.1 uF, 50 V, +/- 20%, X8R, AEC-Q200 Grade 0, 0805", Cap_Case=0805, Manufacturer=TDK, Supplier Part Number 1=445-12821-1-ND, TempCo=X8R, Tolerance_%=20%, Value1=Unknown, Value2=50V, ValueDisplayed=0.1uF
C302 C303 C304 C307 C308 C309 C310 C311 C312 C313 C314 C315 C319 C320 C321 C324 C325 C326 C327 C328 C329 C330 C331 C332 C602 C603 C604 C607 C608 C609 C610 C611 C612 C613 C614 C615 C619 C620 C621 C624 C625 C626 C627 C628 C629 C630 C631 C632: library part CMP-0006309-2, "CAP, CERM, 1000 pF, 50 V, +/- 5%, C0G/NP0, AEC-Q200 Grade 1, 0402", Cap_Case=0402, Manufacturer=TDK, Supplier Part Number 1=445-6885-1-ND, TempCo=C0G/NP0, Tolerance_%=5%, Value1=Unknown, Value2=50V, ValueDisplayed=1000pF
C501 C502: library part CMP-0007075-1, "CAP, CERM, 100 pF, 50 V, +/- 5%, C0G/NP0, AEC-Q200 Grade 0, 0603", Cap_Case=0603, Manufacturer=TDK, Supplier Part Number 1=445-12386-1-ND, TempCo=C0G/NP0, Tolerance_%=5%, Value1=Unknown, Value2=50V, ValueDisplayed=100pF
D300 D301 D302 D303 D304 D305 D306 D307 D308 D309 D310 D311 D312 D313 D314 D315 D316 D317 D318 D319 D320 D321 D322 D323 D324 D325 D326 D327 D328 D329 D330 D331 D332 D333 D334 D335 D336 D337 D338 D339 D340 D341 D342 D343 D344 D345 D346 D347 D600 D601 D602 D603 D604 D605 D606 D607 D608 D609 D610 D611 D612 D613 D614 D615 D616 D617 D618 D619 D620 D621 D622 D623 D624 D625 D626 D627 D628 D629 D630 D631 D632 D633 D634 D635 D636 D637 D638 D639 D640 D641 D642 D643 D644 D645 D646 D647: library part CMP-0002833-3, "LED, Red, SMD", Color=red, Manufacturer=OSRAM, Value1=W, Value2=2.1V
FID1 FID2 FID3: library part CMP-0077181-1, "Fiducial mark.  There is nothing to buy or mount.", Manufacturer=N/A
J100 J400: library part CMP-0055512-1, "Terminal Block, 6x1, 2.54mm, TH", Color=Green, Current_A=6A, Manufacturer="Phoenix Contact", Supplier Part Number 1=277-1277-ND, Voltage_V=160V
L100 L400: library part CMP-0087116-1, "Shielded Power Inductors", Manufacturer=Coilcraft
Logo3: library part CMP-0074847-1, "FCC_disclaimer"
Logo4: library part CMP-0074769-1
R100 R101 R400 R401: library part CMP-0081973-1, "RES, 0, 0%, 0.25 W, AEC-Q200 Grade 0, 0603", Manufacturer=Vishay-Dale, Power_W=250mW, Supplier Part Number 1=541-2779-1-ND, Tolerance_%=0%, Value2=0.25W, Value_Code=0
R204 R207: library part CMP-0021368-3, "RES, 60.4, 1%, 0.125 W, AEC-Q200 Grade 0, 0805", Manufacturer=Vishay-Dale, Power_W=125mW, Supplier Part Number 1=541-60.4CCT-ND, TempCo="100 ppm/C", Tolerance_%=1%, Value2=0.125W, Value_Code=60R4, ValueDisplayed=60.4
R205 R206 R300 R301 R302 R303 R304 R305 R308 R309 R310 R311 R312 R313 R314 R315 R501 R502 R600 R601 R602 R603 R604 R605 R608 R609 R610 R611 R612 R613 R614 R615: library part CMP-0023341-1, "RES, 10.0 k, 1%, 0.1 W, AEC-Q200 Grade 0, 0603", Manufacturer="Stackpole Electronics Inc", Power_W=100mW, Supplier Part Number 1=RMCF0603FT10K0CT-ND, TempCo="100 ppm/C", Tolerance_%=1%, Value2=0.1W, Value_Code=10k0, ValueDisplayed=10.0k
R306 R316 R606 R616: library part CMP-0021550-3, "RES, 12.4 k, 1%, 0.125 W, AEC-Q200 Grade 0, 0805", Manufacturer=Panasonic, Power_W=125mW, Supplier Part Number 1=P12.4KCCT-ND, TempCo="100 ppm/C", Tolerance_%=1%, Value2=0.125W, Value_Code=12k4, ValueDisplayed=12.4k
R500: library part CMP-0021852-1, "RES, 4.70 k, 1%, 0.5 W, AEC-Q200 Grade 0, 0805", Manufacturer=Panasonic, Power_W=500mW, Supplier Part Number 1=P16073CT-ND, TempCo="100 ppm/C", Tolerance_%=1%, Value2=0.5W, Value_Code=4k70, ValueDisplayed=4.70k
R503 R504: library part CMP-0025758-4, "RES, 22, 5%, 0.1 W, AEC-Q200 Grade 0, 0603", Manufacturer=Vishay-Dale, Power_W=100mW, Supplier Part Number 1=541-22GCT-ND, TempCo="200 ppm/C", Tolerance_%=5%, Value2=0.1W, Value_Code=22R0, ValueDisplayed=22
TP300 TP301 TP600 TP601: library part CMP-0003825-1, "1mm Test Point, SMT", Manufacturer=Any
U201: library part CMP-0079882-1, "Automotive High Speed CAN Transceiver, DRB0008F (VSON-8)", Alternate Manufacturer="Texas Instruments", Alternate PartNumber=TCAN1044DRBRQ1
U300 U301 U600 U601: library part CMP-0084207-5, "12-Channel Automotive FlexLED Driver, PWP0024P (HTSSOP-24)", Alternate Manufacturer="Texas Instruments"
U500: library part CMP-0079113-1, "Local Interconnect Network (LIN) Transceiver with Dominant State Timeout, D0008A (SOIC-8)", Alternate Manufacturer="Texas Instruments", Alternate PartNumber=TLIN1029DQ1
ZZ1: library part CMP-0003616-3
ZZ2: library part CMP-0077236-1
ZZ3: library part CMP-0077237-1
ZZ4: library part CMP-0077238-1

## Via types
v1: diameter 0.7, hole 0.3, Top Layer to Bottom Layer, tented both sides, 1881 vias
v2: diameter 0.5, hole 0.2, Top Layer to Bottom Layer, tented both sides, 96 vias

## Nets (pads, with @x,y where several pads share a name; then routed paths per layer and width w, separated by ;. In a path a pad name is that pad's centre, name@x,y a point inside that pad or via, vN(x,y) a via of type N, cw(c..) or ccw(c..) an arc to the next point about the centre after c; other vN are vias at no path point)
1OUT0: C315.2 D302.1 D302.3 D302.4 D302.6 U300.13 | length 54.9
  Bottom Layer w0.35: v1(127.33,5.577) 127.404,5.503 C315.2@127.404,4.561
  Bottom Layer w0.45: U300.13@71.075,14 71.962,14 72.435,13.527 91.11,13.527 91.821,12.816 93.23,12.816 93.236,12.81 101.149,12.81 101.829,12.13 111.557,12.13 112.497,11.19 122.25,11.19 v1(123.342,10.098)
  other v1: 123.342,2.908 124.672,2.908 126.001,2.908 127.33,2.908 123.342,4.281 124.672,4.281 126.001,4.281 123.342,5.577 124.672,5.577 126.001,5.577 124.672,10.098 126.001,10.098 127.33,10.098
1OUT1: C314.2 D306.1 D306.3 D306.4 D306.6 U300.14 | length 45.2
  Bottom Layer w0.254: v1(116.332,5.577) v1@116.392,5.516
  Bottom Layer w0.35: C314.2@116.392,4.535 v1@116.392,5.516
  Bottom Layer w0.45: U300.14@70.425,14 70.425,13.046 70.612,12.859 90.381,12.859 91.211,12.028 100.66,12.028 101.295,11.393 111.049,11.393 v1(112.344,10.098)
  other v1: 112.344,2.91 113.673,2.91 115.003,2.91 116.332,2.91 112.344,4.281 113.673,4.281 115.003,4.281 112.344,5.577 113.673,5.577 115.003,5.577 113.673,10.098 115.003,10.098 116.332,10.098
1OUT2: C313.2 D310.1 D310.3 D310.4 D310.6 U300.15 | length 35.1
  Bottom Layer w0.254: U300.15@69.775,14 U300.15@69.873,13.902 ; v1(105.308,5.577) v1@105.42,5.466
  Bottom Layer w0.35: C313.2@105.42,4.561 v1@105.42,5.466
  Bottom Layer w0.45: U300.15@69.775,14.027 U300.15@69.775,14 69.775,12.73 70.307,12.198 89.594,12.198 90.602,11.19 100.203,11.19 v1(101.321,10.073)
  other v1: 101.321,2.908 102.65,2.908 103.979,2.908 105.308,2.908 101.321,4.281 102.65,4.281 103.979,4.281 101.321,5.577 102.65,5.577 103.979,5.577 102.65,10.073 103.979,10.073 105.308,10.073
1OUT3: C312.2 D314.1 D314.3 D314.4 D314.6 U300.16 | length 24.9
  Bottom Layer w0.254: v1(94.31,5.585) v1@94.404,5.491
  Bottom Layer w0.35: C312.2@94.404,4.535 v1@94.404,5.491
  Bottom Layer w0.45: U300.16@69.125,14 69.125,12.413 70.076,11.462 89.01,11.462 v1(90.399,10.073)
  other v1: 90.399,2.91 91.728,2.91 93.057,2.91 94.386,2.91 90.399,4.281 91.728,4.281 93.057,4.281 90.399,5.577 91.728,5.577 93.057,5.577 91.728,10.073 93.057,10.073 94.386,10.073
1OUT4: C311.2 D318.1 D318.3 D318.4 D318.6 U300.17 | length 14.7
  Bottom Layer w0.254: v1(83.261,5.577) v1@83.372,5.466
  Bottom Layer w0.35: C311.2@83.372,4.535 v1@83.372,5.466
  Bottom Layer w0.45: U300.17@68.475,14 68.475,11.973 69.672,10.776 78.57,10.776 v1(79.273,10.073)
  other v1: 79.273,2.91 80.603,2.91 81.932,2.91 83.261,2.91 79.273,4.281 80.603,4.281 81.932,4.281 79.273,5.577 80.603,5.577 81.932,5.577 80.603,10.073 81.932,10.073 83.261,10.073
1OUT5: C310.2 D322.1 D322.3 D322.4 D322.6 U300.18 | length 5.5
  Bottom Layer w0.254: v1(72.39,5.577) v1@72.404,5.563
  Bottom Layer w0.35: C310.2@72.404,4.535 v1@72.404,5.563
  Bottom Layer w0.45: U300.18@67.825,14 67.825,10.32 68.275,9.869 v1(68.402,9.869)
  other v1: 68.402,2.91 69.731,2.91 71.061,2.91 72.39,2.91 68.402,4.281 69.731,4.281 71.061,4.281 68.402,5.577 69.731,5.577 71.061,5.577 69.731,9.869 71.061,9.869 72.39,9.869
1OUT6: C309.2 D301.1 D301.3 D301.4 D301.6 U300.19 | length 5.2
  Bottom Layer w0.254: v1@63.059,5.567 v1(63.068,5.577)
  Bottom Layer w0.35: C309.2@63.059,4.535 v1@63.059,5.567
  Bottom Layer w0.45: v1(67.056,9.869) 67.175,9.988 U300.19@67.175,14
  other v1: 63.068,2.91 64.397,2.91 65.727,2.91 67.056,2.91 64.397,4.281 65.727,4.281 67.056,4.281 64.397,5.577 65.727,5.577 67.056,5.577 63.068,9.869 64.397,9.869 65.727,9.869
1OUT7: C308.2 D305.1 D305.3 D305.4 D305.6 U300.20 | length 14.4
  Bottom Layer w0.254: v1(52.019,5.577) v1@52.059,5.537
  Bottom Layer w0.35: C308.2@52.059,4.535 v1@52.059,5.537
  Bottom Layer w0.45: v1@56.007,10.098 56.617,10.708 65.253,10.708 66.525,11.98 U300.20@66.525,14
  other v1: 52.019,2.908 53.348,2.908 54.678,2.908 56.007,2.908 53.348,4.281 54.678,4.281 56.007,4.281 53.348,5.577 54.678,5.577 56.007,5.577 52.019,10.073 53.348,10.073 54.678,10.073 56.007,10.073
1OUT8: C307.2 D309.1 D309.3 D309.4 D309.6 U300.21 | length 24.4
  Bottom Layer w0.254: v1@41.059,5.513 v1(41.123,5.577)
  Bottom Layer w0.35: C307.2@41.059,4.535 v1@41.059,5.513
  Bottom Layer w0.45: v1(45.11,10.073) 46.507,11.47 64.922,11.47 65.875,12.422 U300.21@65.875,14
  other v1: 41.123,2.908 42.452,2.908 43.781,2.908 45.11,2.908 42.452,4.281 43.781,4.281 45.11,4.281 42.452,5.577 43.781,5.577 45.11,5.577 41.123,10.073 42.452,10.073 43.781,10.073
1OUT9: C304.2 D313.1 D313.3 D313.4 D313.6 U300.22 | length 34.6
  Bottom Layer w0.254: v1@30.059,5.511 v1(30.124,5.577)
  Bottom Layer w0.35: C304.2@30.059,4.535 v1@30.059,5.511
  Bottom Layer w0.45: v1(34.112,10.098) 35.154,11.139 44.806,11.139 45.847,12.181 64.714,12.181 65.225,12.691 65.225,13.153 U300.22@65.225,14
  other v1: 30.124,2.908 31.454,2.908 32.783,2.908 34.112,2.908 31.454,4.281 32.783,4.281 34.112,4.281 31.454,5.577 32.783,5.577 34.112,5.577 30.124,10.098 31.454,10.098 32.783,10.098
1OUT10: C303.2 D317.1 D317.3 D317.4 D317.6 U300.23 | length 44.7
  Bottom Layer w0.254: v1@19.059,5.535 v1(19.101,5.577)
  Bottom Layer w0.35: C303.2@19.059,4.535 v1@19.059,5.535
  Bottom Layer w0.45: v1(23.089,10.098) 24.13,11.139 33.833,11.139 34.544,11.851 44.399,11.851 45.39,12.841 64.313,12.841 64.575,13.103 U300.23@64.575,14
  other v1: 19.101,2.908 20.43,2.908 21.759,2.908 23.089,2.908 20.43,4.256 21.759,4.256 23.089,4.256 20.43,5.577 21.759,5.577 23.089,5.577 19.101,10.098 20.43,10.098 21.759,10.098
